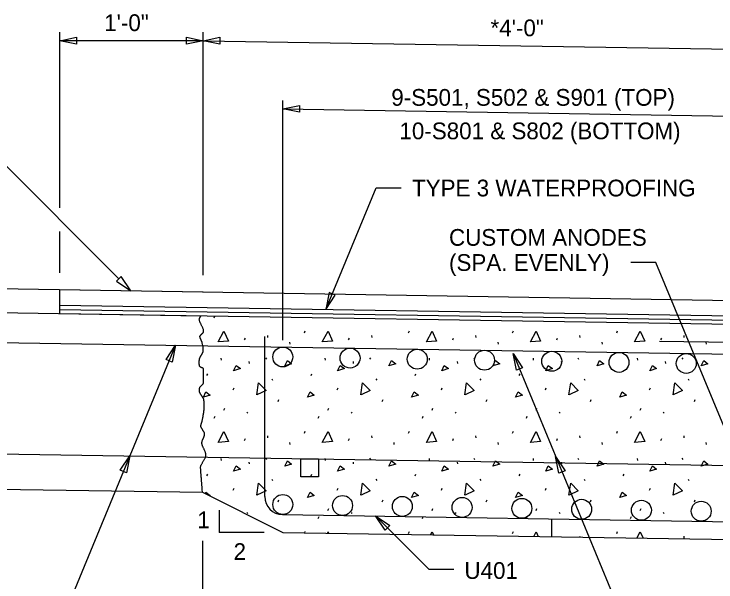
# Model space of a CAD drawing. Extents: x -2063 to 2068, y 79 to 1202.
# Drawn here: x -576.36 to -547, y 259.37 to 283.1 of the extents above; entities that cross this region are included whole.
import ezdxf

# ---------------------------------------------------------------- set-up
doc = ezdxf.new("R2010")
doc.units = 0
for name, color, linetype in [('BR_P_Gen_Joint_Filler', 7, 'Continuous'), ('BR_P_Gen_Text', 7, 'Continuous'), ('BR_P_Gen_Utilities', 7, 'Continuous'), ('BR_P_Slab_Object', 7, 'Continuous'), ('BR_P_Slab_Reinforcing', 7, 'Continuous'), ('BR_P_Sub_Reinforcing', 7, 'Continuous'), ('BR_X_Slab_Object', 7, 'Continuous'), ('BR_X_Slab_Reinforcing', 7, 'Continuous'), ('SH_Text', 7, 'Continuous')]:
    doc.layers.add(name, color=color, linetype=linetype)

msp = doc.modelspace()

# ---------------------------------------------------------------- linework, layer by layer
at = {"layer": 'BR_P_Gen_Joint_Filler'}
for p, q in [((-574.445, 270.935), (-541.474, 270.408)), ((-574.442, 270.76), (-541.296, 270.23))]:
    msp.add_line(p, q, dxfattribs=at)
at = {"layer": 'BR_P_Gen_Text'}
for p, q in [((-574.445, 274.998), (-574.445, 282.341)), ((-568.445, 272.19), (-568.445, 282.341)), ((-568.445, 281.991), (-574.445, 281.991)), ((-568.445, 281.991), (-541.119, 281.554)), ((-565.119, 269.469), (-565.119, 279.487)), ((-565.119, 279.137), (-542.619, 278.777)), ((-571.975, 272.033), (-577.73, 277.788)), ((-563.32, 270.757), (-561.215, 275.839)), ((-561.215, 275.839), (-560.165, 275.839)), ((-574.445, 272.286), (-574.445, 274.008)), ((-549.51, 272.715), (-550.56, 272.715)), ((-545.994, 264.225), (-549.51, 272.715)), ((-567.986, 270.411), (-567.955, 270.482)), ((-563.633, 270.411), (-563.633, 270.412)), ((-564.213, 269.784), (-564.177, 269.864)), ((-559.86, 269.784), (-559.824, 269.864)), ((-555.507, 269.784), (-555.471, 269.864)), ((-551.154, 269.784), (-551.118, 269.864)), ((-566.717, 269.48), (-566.682, 269.56)), ((-565.763, 269.664), (-565.754, 269.584)), ((-562.364, 269.48), (-562.329, 269.56)), ((-561.41, 269.664), (-561.401, 269.584)), ((-558.011, 269.48), (-557.976, 269.56)), ((-557.057, 269.664), (-557.048, 269.584)), ((-553.658, 269.48), (-553.623, 269.56)), ((-552.704, 269.664), (-552.696, 269.584)), ((-549.306, 269.48), (-549.27, 269.56)), ((-548.352, 269.664), (-548.343, 269.584)), ((-569.6, 269.258), (-574.398, 257.676)), ((-564.831, 269.39), (-564.822, 269.31)), ((-556.125, 269.39), (-556.116, 269.31)), ((-551.772, 269.39), (-551.763, 269.31)), ((-547.419, 269.39), (-547.41, 269.31)), ((-555.488, 268.913), (-549.094, 253.476)), ((-567.709, 268.715), (-567.7, 268.635)), ((-565.839, 268.738), (-565.803, 268.684)), ((-563.356, 268.715), (-563.347, 268.635)), ((-561.486, 268.738), (-561.45, 268.684)), ((-559.003, 268.715), (-558.994, 268.635)), ((-557.133, 268.738), (-557.097, 268.684)), ((-554.65, 268.715), (-554.641, 268.635)), ((-552.78, 268.738), (-552.744, 268.684)), ((-550.297, 268.715), (-550.288, 268.635)), ((-548.427, 268.738), (-548.392, 268.684)), ((-566.533, 268.574), (-566.524, 268.494)), ((-562.18, 268.574), (-562.171, 268.494)), ((-557.827, 268.574), (-557.818, 268.494)), ((-553.474, 268.574), (-553.465, 268.494)), ((-549.121, 268.574), (-549.112, 268.494)), ((-568.291, 267.99), (-568.255, 268.07)), ((-563.938, 267.99), (-563.902, 268.07)), ((-559.585, 267.99), (-559.549, 268.07)), ((-555.232, 267.99), (-555.196, 268.07)), ((-565.578, 267.858), (-565.542, 267.805)), ((-561.225, 267.858), (-561.189, 267.805)), ((-556.872, 267.858), (-556.836, 267.805)), ((-552.519, 267.858), (-552.483, 267.805)), ((-548.166, 267.858), (-548.13, 267.805)), ((-567.193, 267.402), (-567.157, 267.482)), ((-562.84, 267.402), (-562.804, 267.482)), ((-558.487, 267.402), (-558.451, 267.482)), ((-554.134, 267.402), (-554.098, 267.482)), ((-549.781, 267.402), (-549.746, 267.482)), ((-565.313, 266.907), (-565.277, 266.987)), ((-560.96, 266.907), (-560.924, 266.987)), ((-556.607, 266.907), (-556.571, 266.987)), ((-552.254, 266.907), (-552.218, 266.987)), ((-547.901, 266.907), (-547.865, 266.987)), ((-567.582, 266.552), (-567.546, 266.632)), ((-563.229, 266.552), (-563.193, 266.632)), ((-558.876, 266.552), (-558.841, 266.632)), ((-554.523, 266.552), (-554.488, 266.632)), ((-550.17, 266.552), (-550.135, 266.632)), ((-567.986, 266.216), (-567.951, 266.296)), ((-566.617, 266.469), (-566.582, 266.416)), ((-563.633, 266.216), (-563.598, 266.296)), ((-562.264, 266.469), (-562.229, 266.416)), ((-559.28, 266.216), (-559.245, 266.296)), ((-557.911, 266.469), (-557.876, 266.416)), ((-554.927, 266.216), (-554.892, 266.296)), ((-553.558, 266.469), (-553.523, 266.416)), ((-550.575, 266.216), (-550.539, 266.296)), ((-549.206, 266.469), (-549.17, 266.416)), ((-565.763, 265.469), (-565.754, 265.389)), ((-564.213, 265.589), (-564.177, 265.669)), ((-561.41, 265.469), (-561.401, 265.389)), ((-559.86, 265.589), (-559.824, 265.669)), ((-557.057, 265.469), (-557.048, 265.389)), ((-555.507, 265.589), (-555.471, 265.669)), ((-552.704, 265.469), (-552.696, 265.389)), ((-551.154, 265.589), (-551.118, 265.669)), ((-548.352, 265.469), (-548.343, 265.389)), ((-566.717, 265.285), (-566.682, 265.365)), ((-564.831, 265.195), (-564.822, 265.115)), ((-562.364, 265.285), (-562.329, 265.365)), ((-560.478, 265.195), (-560.469, 265.115)), ((-558.011, 265.285), (-557.976, 265.365)), ((-556.125, 265.195), (-556.116, 265.115)), ((-553.658, 265.285), (-553.623, 265.365)), ((-551.772, 265.195), (-551.763, 265.115)), ((-549.306, 265.285), (-549.27, 265.365)), ((-547.419, 265.195), (-547.41, 265.115)), ((-554.019, 264.957), (-554.018, 264.955)), ((-567.709, 264.52), (-567.7, 264.44)), ((-565.839, 264.543), (-565.803, 264.489)), ((-563.356, 264.52), (-563.347, 264.44)), ((-561.486, 264.543), (-561.45, 264.489)), ((-559.003, 264.52), (-558.994, 264.44)), ((-557.133, 264.543), (-557.097, 264.489)), ((-554.65, 264.52), (-554.641, 264.44)), ((-552.78, 264.543), (-552.744, 264.489)), ((-550.297, 264.52), (-550.288, 264.44)), ((-548.427, 264.543), (-548.392, 264.489)), ((-566.533, 264.379), (-566.524, 264.299)), ((-562.18, 264.379), (-562.171, 264.299)), ((-557.827, 264.379), (-557.818, 264.299)), ((-553.474, 264.379), (-553.465, 264.299)), ((-549.121, 264.379), (-549.112, 264.299)), ((-568.291, 263.795), (-568.255, 263.875)), ((-565.578, 263.663), (-565.542, 263.61)), ((-563.938, 263.795), (-563.902, 263.875)), ((-561.225, 263.663), (-561.189, 263.61)), ((-559.585, 263.795), (-559.549, 263.875)), ((-556.872, 263.663), (-556.836, 263.61)), ((-555.232, 263.795), (-555.196, 263.875)), ((-552.519, 263.663), (-552.483, 263.61)), ((-550.879, 263.795), (-550.844, 263.875)), ((-548.166, 263.663), (-548.13, 263.61)), ((-567.193, 263.207), (-567.157, 263.287)), ((-562.84, 263.207), (-562.804, 263.287)), ((-558.487, 263.207), (-558.451, 263.287)), ((-554.134, 263.207), (-554.098, 263.287)), ((-549.781, 263.207), (-549.746, 263.287)), ((-565.313, 262.712), (-565.277, 262.792)), ((-560.96, 262.712), (-560.924, 262.792)), ((-556.607, 262.712), (-556.571, 262.792)), ((-552.254, 262.712), (-552.218, 262.792)), ((-547.901, 262.712), (-547.865, 262.792)), ((-567.776, 262.372), (-567.776, 261.435)), ((-566.617, 262.274), (-566.582, 262.221)), ((-563.229, 262.357), (-563.193, 262.437)), ((-562.264, 262.274), (-562.229, 262.221)), ((-558.876, 262.357), (-558.841, 262.437)), ((-557.911, 262.274), (-557.876, 262.221)), ((-554.523, 262.357), (-554.488, 262.437)), ((-553.558, 262.274), (-553.523, 262.221)), ((-550.17, 262.357), (-550.135, 262.437)), ((-549.206, 262.274), (-549.17, 262.221)), ((-563.633, 262.021), (-563.598, 262.1)), ((-559.28, 262.021), (-559.245, 262.1)), ((-554.927, 262.021), (-554.892, 262.1)), ((-550.575, 262.021), (-550.539, 262.1)), ((-565.901, 261.435), (-567.776, 261.435)), ((-564.201, 261.42), (-564.177, 261.474)), ((-559.86, 261.394), (-559.824, 261.474)), ((-555.507, 261.394), (-555.471, 261.474)), ((-551.154, 261.394), (-551.118, 261.474)), ((-568.476, 261.085), (-568.476, 257.326)), ((-552.704, 261.274), (-552.7, 261.236)), ((-548.352, 261.274), (-548.343, 261.194))]:
    msp.add_line(p, q, dxfattribs=at)
for points in [[(-573.745, 281.851), (-574.445, 281.991), (-573.745, 282.131)], [(-569.145, 282.131), (-568.445, 281.991), (-569.145, 281.851)], [(-567.745, 281.851), (-568.445, 281.991), (-567.745, 282.131)], [(-564.419, 278.997), (-565.119, 279.137), (-564.419, 279.277)], [(-572.074, 271.934), (-571.48, 271.538), (-571.876, 272.132)], [(-563.182, 271.458), (-563.32, 270.757), (-562.923, 271.351)], [(-569.997, 268.665), (-569.6, 269.258), (-569.739, 268.557)], [(-555.35, 268.213), (-555.488, 268.913), (-555.091, 268.32)], [(-571.913, 264.041), (-571.516, 264.634), (-571.654, 263.933)], [(-553.567, 263.91), (-553.706, 264.61), (-553.309, 264.017)]]:
    msp.add_lwpolyline(points, close=True, dxfattribs=at)
for points in [[(-567.82, 269.396), (-567.58, 269.849), (-567.394, 269.432), (-567.811, 269.396)], [(-563.467, 269.396), (-563.227, 269.849), (-563.041, 269.432), (-563.458, 269.396)], [(-559.114, 269.396), (-558.874, 269.849), (-558.688, 269.432), (-559.105, 269.396)], [(-554.761, 269.396), (-554.521, 269.849), (-554.335, 269.432), (-554.752, 269.396)], [(-550.408, 269.396), (-550.168, 269.849), (-549.982, 269.432), (-550.399, 269.396)], [(-567.178, 268.193), (-567.072, 268.415), (-566.894, 268.281), (-567.178, 268.193)], [(-565.034, 268.395), (-564.927, 268.617), (-564.749, 268.484), (-565.034, 268.395)], [(-562.825, 268.193), (-562.719, 268.415), (-562.541, 268.281), (-562.825, 268.193)], [(-560.681, 268.395), (-560.574, 268.617), (-560.396, 268.484), (-560.681, 268.395)], [(-558.472, 268.193), (-558.366, 268.415), (-558.188, 268.281), (-558.472, 268.193)], [(-556.328, 268.395), (-556.221, 268.617), (-556.044, 268.484), (-556.328, 268.395)], [(-554.119, 268.193), (-554.013, 268.415), (-553.835, 268.281), (-554.119, 268.193)], [(-551.975, 268.395), (-551.868, 268.617), (-551.691, 268.484), (-551.975, 268.395)], [(-549.766, 268.193), (-549.66, 268.415), (-549.482, 268.281), (-549.766, 268.193)], [(-547.622, 268.395), (-547.515, 268.617), (-547.338, 268.484), (-547.622, 268.395)], [(-566.207, 267.187), (-566.137, 267.694), (-565.819, 267.366), (-566.199, 267.19)], [(-561.854, 267.187), (-561.784, 267.694), (-561.466, 267.366), (-561.846, 267.19)], [(-557.501, 267.187), (-557.431, 267.694), (-557.113, 267.366), (-557.493, 267.19)], [(-553.148, 267.187), (-553.078, 267.694), (-552.76, 267.366), (-553.14, 267.19)], [(-548.795, 267.187), (-548.725, 267.694), (-548.407, 267.366), (-548.787, 267.19)], [(-568.438, 267.087), (-568.332, 267.309), (-568.154, 267.176), (-568.438, 267.087)], [(-564.085, 267.087), (-563.979, 267.309), (-563.801, 267.176), (-564.085, 267.087)], [(-559.732, 267.087), (-559.626, 267.309), (-559.448, 267.176), (-559.732, 267.087)], [(-555.379, 267.087), (-555.273, 267.309), (-555.095, 267.176), (-555.379, 267.087)], [(-551.027, 267.087), (-550.92, 267.309), (-550.742, 267.176), (-551.027, 267.087)], [(-567.82, 265.201), (-567.58, 265.654), (-567.394, 265.236), (-567.811, 265.201)], [(-563.467, 265.201), (-563.227, 265.654), (-563.041, 265.236), (-563.458, 265.201)], [(-559.114, 265.201), (-558.874, 265.654), (-558.688, 265.236), (-559.105, 265.201)], [(-554.761, 265.201), (-554.521, 265.654), (-554.335, 265.236), (-554.752, 265.201)], [(-550.408, 265.201), (-550.168, 265.654), (-549.982, 265.236), (-550.399, 265.201)], [(-567.178, 263.997), (-567.072, 264.219), (-566.894, 264.086), (-567.178, 263.997)], [(-565.034, 264.2), (-564.927, 264.422), (-564.749, 264.289), (-565.034, 264.2)], [(-562.825, 263.997), (-562.719, 264.219), (-562.541, 264.086), (-562.825, 263.997)], [(-560.681, 264.2), (-560.574, 264.422), (-560.396, 264.289), (-560.681, 264.2)], [(-558.472, 263.997), (-558.366, 264.219), (-558.188, 264.086), (-558.472, 263.997)], [(-556.328, 264.2), (-556.221, 264.422), (-556.044, 264.289), (-556.328, 264.2)], [(-554.119, 263.997), (-554.013, 264.219), (-553.835, 264.086), (-554.119, 263.997)], [(-551.975, 264.2), (-551.868, 264.422), (-551.691, 264.289), (-551.975, 264.2)], [(-549.766, 263.997), (-549.66, 264.219), (-549.482, 264.086), (-549.766, 263.997)], [(-547.622, 264.2), (-547.515, 264.422), (-547.338, 264.289), (-547.622, 264.2)], [(-566.207, 262.991), (-566.137, 263.499), (-565.819, 263.171), (-566.199, 262.994)], [(-561.854, 262.991), (-561.784, 263.499), (-561.466, 263.171), (-561.846, 262.994)], [(-557.501, 262.991), (-557.431, 263.499), (-557.113, 263.171), (-557.493, 262.994)], [(-553.148, 262.991), (-553.078, 263.499), (-552.76, 263.171), (-553.14, 262.994)], [(-548.795, 262.991), (-548.725, 263.499), (-548.407, 263.171), (-548.787, 262.994)], [(-568.36, 263.056), (-568.332, 263.114), (-568.154, 262.98), (-568.188, 262.97)], [(-564.085, 262.892), (-563.979, 263.114), (-563.801, 262.98), (-564.085, 262.892)], [(-559.732, 262.892), (-559.626, 263.114), (-559.448, 262.98), (-559.732, 262.892)], [(-555.379, 262.892), (-555.273, 263.114), (-555.095, 262.98), (-555.379, 262.892)], [(-551.027, 262.892), (-550.92, 263.114), (-550.742, 262.98), (-551.027, 262.892)], [(-563.255, 261.405), (-563.227, 261.459), (-563.203, 261.404)], [(-558.939, 261.336), (-558.874, 261.459), (-558.819, 261.334)], [(-554.623, 261.267), (-554.521, 261.459), (-554.434, 261.264)], [(-550.306, 261.198), (-550.168, 261.459), (-550.05, 261.194)]]:
    msp.add_lwpolyline(points, dxfattribs=at)
at = {"layer": 'BR_P_Gen_Utilities'}
msp.add_lwpolyline([(-564.368, 264.513), (-563.619, 264.513), (-563.619, 263.764), (-564.368, 263.764)], close=True, dxfattribs=at)
at = {"layer": 'BR_P_Slab_Object'}
for p, q in [((-574.445, 271.586), (-542.135, 271.069)), ((-574.445, 270.585), (-574.445, 271.586)), ((-574.445, 270.585), (-541.119, 270.052)), ((-568.476, 263.114), (-565.119, 261.435)), ((-565.119, 261.435), (-542.869, 261.079))]:
    msp.add_line(p, q, dxfattribs=at)
msp.add_open_spline([(-568.476, 263.114), (-568.503, 263.446), (-568.529, 263.778), (-568.556, 264.111), (-568.56, 264.159), (-568.552, 264.207), (-568.53, 264.252), (-568.508, 264.3), (-568.483, 264.343), (-568.457, 264.387), (-568.432, 264.432), (-568.404, 264.474), (-568.378, 264.52), (-568.355, 264.562), (-568.341, 264.609), (-568.335, 264.656), (-568.332, 264.678), (-568.334, 264.7), (-568.338, 264.721), (-568.342, 264.743), (-568.346, 264.766), (-568.354, 264.786), (-568.373, 264.83), (-568.393, 264.873), (-568.412, 264.917), (-568.432, 264.96), (-568.453, 265.003), (-568.473, 265.047), (-568.486, 265.078), (-568.493, 265.111), (-568.499, 265.145), (-568.501, 265.156), (-568.502, 265.167), (-568.501, 265.178), (-568.499, 265.209), (-568.496, 265.241), (-568.484, 265.27), (-568.471, 265.301), (-568.457, 265.332), (-568.444, 265.363), (-568.431, 265.394), (-568.418, 265.425), (-568.406, 265.456), (-568.394, 265.485), (-568.388, 265.518), (-568.39, 265.548), (-568.391, 265.58), (-568.402, 265.612), (-568.419, 265.641), (-568.438, 265.673), (-568.458, 265.701), (-568.477, 265.732), (-568.495, 265.762), (-568.513, 265.79), (-568.53, 265.822), (-568.544, 265.851), (-568.549, 265.884), (-568.543, 265.915), (-568.539, 265.931), (-568.535, 265.948), (-568.53, 265.964), (-568.525, 265.98), (-568.52, 265.996), (-568.514, 266.013), (-568.509, 266.029), (-568.504, 266.046), (-568.498, 266.063), (-568.493, 266.079), (-568.489, 266.096), (-568.486, 266.113), (-568.472, 266.178), (-568.46, 266.244), (-568.449, 266.31), (-568.437, 266.376), (-568.427, 266.442), (-568.417, 266.509), (-568.412, 266.546), (-568.408, 266.584), (-568.406, 266.621), (-568.403, 266.659), (-568.402, 266.697), (-568.402, 266.735), (-568.402, 266.773), (-568.404, 266.811), (-568.406, 266.849), (-568.408, 266.887), (-568.412, 266.924), (-568.417, 266.961), (-568.422, 266.993), (-568.431, 267.024), (-568.447, 267.052), (-568.464, 267.081), (-568.482, 267.108), (-568.5, 267.136), (-568.519, 267.163), (-568.538, 267.19), (-568.556, 267.218), (-568.574, 267.245), (-568.586, 267.273), (-568.596, 267.305), (-568.604, 267.332), (-568.606, 267.359), (-568.606, 267.387), (-568.606, 267.414), (-568.605, 267.442), (-568.596, 267.469), (-568.588, 267.493), (-568.576, 267.514), (-568.559, 267.533), (-568.541, 267.553), (-568.522, 267.571), (-568.504, 267.59), (-568.486, 267.609), (-568.469, 267.627), (-568.453, 267.649), (-568.439, 267.669), (-568.431, 267.693), (-568.431, 267.716), (-568.431, 267.789), (-568.431, 267.863), (-568.431, 267.936), (-568.431, 268.041), (-568.431, 268.146), (-568.431, 268.251), (-568.431, 268.267), (-568.44, 268.285), (-568.454, 268.294), (-568.471, 268.305), (-568.489, 268.313), (-568.506, 268.322), (-568.525, 268.331), (-568.544, 268.339), (-568.562, 268.349), (-568.577, 268.358), (-568.59, 268.372), (-568.596, 268.389), (-568.6, 268.401), (-568.602, 268.414), (-568.605, 268.426), (-568.607, 268.439), (-568.609, 268.452), (-568.611, 268.465), (-568.614, 268.492), (-568.615, 268.519), (-568.615, 268.546), (-568.615, 268.573), (-568.613, 268.6), (-568.61, 268.627), (-568.607, 268.653), (-568.603, 268.679), (-568.596, 268.704), (-568.587, 268.734), (-568.575, 268.763), (-568.56, 268.79), (-568.545, 268.819), (-568.527, 268.846), (-568.511, 268.874), (-568.495, 268.902), (-568.48, 268.929), (-568.466, 268.959), (-568.453, 268.987), (-568.445, 269.017), (-568.445, 269.047), (-568.443, 269.148), (-568.46, 269.251), (-568.488, 269.351), (-568.494, 269.374), (-568.5, 269.396), (-568.509, 269.417), (-568.518, 269.439), (-568.527, 269.461), (-568.536, 269.483), (-568.546, 269.504), (-568.554, 269.525), (-568.563, 269.547), (-568.572, 269.567), (-568.578, 269.589), (-568.582, 269.61), (-568.585, 269.629), (-568.579, 269.649), (-568.566, 269.667), (-568.55, 269.69), (-568.534, 269.703), (-568.516, 269.72), (-568.498, 269.738), (-568.479, 269.755), (-568.461, 269.773), (-568.453, 269.781), (-568.447, 269.79), (-568.441, 269.801), (-568.436, 269.81), (-568.432, 269.82), (-568.431, 269.829), (-568.427, 269.874), (-568.435, 269.923), (-568.455, 269.966), (-568.478, 270.015), (-568.504, 270.061), (-568.528, 270.11), (-568.55, 270.158), (-568.573, 270.206), (-568.593, 270.255), (-568.611, 270.297), (-568.611, 270.349), (-568.596, 270.392), (-568.588, 270.413), (-568.577, 270.433), (-568.563, 270.451), (-568.552, 270.464), (-568.541, 270.477), (-568.53, 270.491)], degree=3, dxfattribs=at)
at = {"layer": 'BR_P_Slab_Reinforcing'}
for p, q in [((-565.869, 262.935), (-565.869, 269.632)), ((-549.369, 269.434), (-542.607, 269.326)), ((-565.131, 262.185), (-542.631, 261.825))]:
    msp.add_line(p, q, dxfattribs=at)
msp.add_arc((-565.119, 262.935), 0.75, 180, 269.0833, dxfattribs=at)
at = {"layer": 'BR_P_Sub_Reinforcing'}
for centre in [(-565.119, 268.769), (-562.306, 268.724), (-559.494, 268.679), (-556.681, 268.634), (-553.869, 268.589), (-551.056, 268.544), (-548.244, 268.499), (-565.119, 262.602), (-562.619, 262.562), (-560.119, 262.522), (-557.619, 262.482), (-555.119, 262.442), (-552.619, 262.402), (-550.119, 262.362), (-547.619, 262.322)]:
    msp.add_circle(centre, 0.417, dxfattribs=at)
at = {"layer": 'BR_X_Slab_Object'}
for p, q in [((-578.445, 271.65), (-568.445, 271.49)), ((-578.445, 270.649), (-568.53, 270.491)), ((-578.445, 263.273), (-568.476, 263.114))]:
    msp.add_line(p, q, dxfattribs=at)
at = {"layer": 'BR_X_Slab_Reinforcing'}
for p, q in [((-578.445, 269.399), (-542.119, 268.818)), ((-578.445, 264.745), (-542.119, 264.163)), ((-553.881, 262.005), (-553.881, 261.255))]:
    msp.add_line(p, q, dxfattribs=at)
at = {"layer": 'SH_Text'}
for p, q in [((-561.239, 262.123), (-559.011, 259.896)), ((-559.011, 259.896), (-557.961, 259.896))]:
    msp.add_line(p, q, dxfattribs=at)
msp.add_lwpolyline([(-560.84, 261.531), (-561.239, 262.123), (-560.643, 261.73)], close=True, dxfattribs=at)

# ---------------------------------------------------------------- texts
at = {"layer": 'BR_P_Gen_Text'}
for s, height, p in [('1\'-0"', 0.7, (-572.589, 282.393)), ('*4\'-0"', 0.7, (-556.43, 282.175)), ('9-S501, S502 & S901 (TOP)', 0.7, (-560.58, 279.27)), ('10-S801 & S802 (BOTTOM)', 0.7, (-560.239, 277.87)), ('TYPE 3 WATERPROOFING', 0.70011, (-559.714, 275.481)), ('CUSTOM ANODES', 0.70011, (-558.167, 273.417)), ('(SPA. EVENLY)', 0.70011, (-558.167, 272.367)), ('1', 0.7, (-568.693, 261.611)), ('2', 0.7, (-567.177, 260.285)), ('U401', 0.7, (-557.522, 259.493))]:
    msp.add_text(s, height=height, dxfattribs=at).set_placement(p)

doc.saveas('drawing.dxf')
